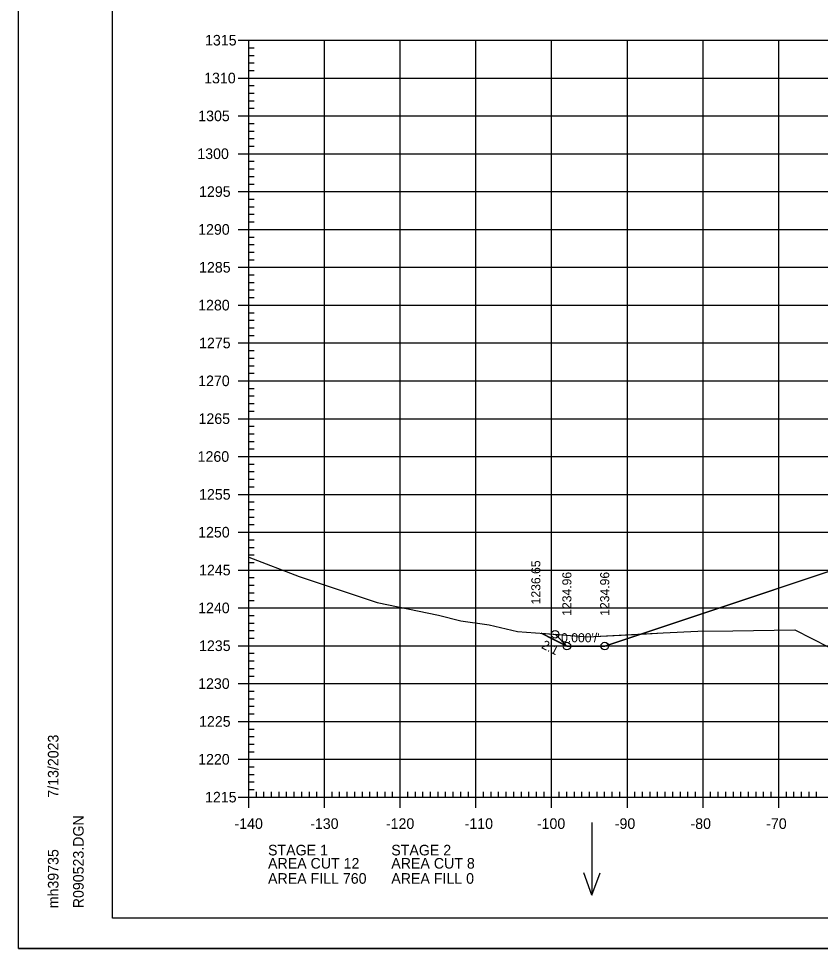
# Model space of a CAD drawing. Extents: x 1406028 to 1412453, y 321733 to 325986.
# Drawn here: x 1406419.5 to 1406525.4, y 324279.4 to 324402.2 of the extents above; entities that cross this region are included whole.
import ezdxf

# ---------------------------------------------------------------- set-up
doc = ezdxf.new("R2010")
doc.units = 0
for name, color, linetype in [('R_Axis', 7, 'Continuous'), ('R_Axis Annot', 7, 'Continuous'), ('R_Border', 7, 'Continuous'), ('R_Exist Surface', 7, 'Continuous'), ('R_Fin Surface', 7, 'Continuous'), ('R_Fin Surface Annot', 7, 'Continuous'), ('R_Grid', 7, 'Continuous'), ('R_No Plot', 7, 'Continuous'), ('R_Proposed Const Limits', 7, 'Continuous'), ('R_Proposed Road', 7, 'Continuous'), ('R_Water Annot', 7, 'Continuous')]:
    doc.layers.add(name, color=color, linetype=linetype)

msp = doc.modelspace()

# ---------------------------------------------------------------- linework, layer by layer
at = {"layer": 'R_Axis'}
for p, q in [((1406448.49, 324399.37), (1406451.29, 324399.37)), ((1406449.89, 324299.37), (1406449.89, 324399.37)), ((1406449.89, 324398.37), (1406450.59, 324398.37)), ((1406449.89, 324397.37), (1406450.59, 324397.37)), ((1406449.89, 324396.37), (1406450.59, 324396.37)), ((1406449.89, 324395.37), (1406450.59, 324395.37)), ((1406448.49, 324394.37), (1406451.29, 324394.37)), ((1406449.89, 324393.37), (1406450.59, 324393.37)), ((1406449.89, 324392.37), (1406450.59, 324392.37)), ((1406449.89, 324391.37), (1406450.59, 324391.37)), ((1406449.89, 324390.37), (1406450.59, 324390.37)), ((1406448.49, 324389.37), (1406451.29, 324389.37)), ((1406449.89, 324388.37), (1406450.59, 324388.37)), ((1406449.89, 324387.37), (1406450.59, 324387.37)), ((1406449.89, 324386.37), (1406450.59, 324386.37)), ((1406449.89, 324385.37), (1406450.59, 324385.37)), ((1406448.49, 324384.37), (1406451.29, 324384.37)), ((1406449.89, 324383.37), (1406450.59, 324383.37)), ((1406449.89, 324382.37), (1406450.59, 324382.37)), ((1406449.89, 324381.37), (1406450.59, 324381.37)), ((1406449.89, 324380.37), (1406450.59, 324380.37)), ((1406448.49, 324379.37), (1406451.29, 324379.37)), ((1406449.89, 324378.37), (1406450.59, 324378.37)), ((1406449.89, 324377.37), (1406450.59, 324377.37)), ((1406449.89, 324376.37), (1406450.59, 324376.37)), ((1406449.89, 324375.37), (1406450.59, 324375.37)), ((1406448.49, 324374.37), (1406451.29, 324374.37)), ((1406449.89, 324373.37), (1406450.59, 324373.37)), ((1406449.89, 324372.37), (1406450.59, 324372.37)), ((1406449.89, 324371.37), (1406450.59, 324371.37)), ((1406449.89, 324370.37), (1406450.59, 324370.37)), ((1406448.49, 324369.37), (1406451.29, 324369.37)), ((1406449.89, 324368.37), (1406450.59, 324368.37)), ((1406449.89, 324367.37), (1406450.59, 324367.37)), ((1406449.89, 324366.37), (1406450.59, 324366.37)), ((1406449.89, 324365.37), (1406450.59, 324365.37)), ((1406448.49, 324364.37), (1406451.29, 324364.37)), ((1406449.89, 324363.37), (1406450.59, 324363.37)), ((1406449.89, 324362.37), (1406450.59, 324362.37)), ((1406449.89, 324361.37), (1406450.59, 324361.37)), ((1406449.89, 324360.37), (1406450.59, 324360.37)), ((1406448.49, 324359.37), (1406451.29, 324359.37)), ((1406449.89, 324358.37), (1406450.59, 324358.37)), ((1406449.89, 324357.37), (1406450.59, 324357.37)), ((1406449.89, 324356.37), (1406450.59, 324356.37)), ((1406449.89, 324355.37), (1406450.59, 324355.37)), ((1406448.49, 324354.37), (1406451.29, 324354.37)), ((1406449.89, 324353.37), (1406450.59, 324353.37)), ((1406449.89, 324352.37), (1406450.59, 324352.37)), ((1406449.89, 324351.37), (1406450.59, 324351.37)), ((1406449.89, 324350.37), (1406450.59, 324350.37)), ((1406448.49, 324349.37), (1406451.29, 324349.37)), ((1406449.89, 324348.37), (1406450.59, 324348.37)), ((1406449.89, 324347.37), (1406450.59, 324347.37)), ((1406449.89, 324346.37), (1406450.59, 324346.37)), ((1406448.49, 324344.37), (1406451.29, 324344.37)), ((1406449.89, 324345.37), (1406450.59, 324345.37)), ((1406449.89, 324343.37), (1406450.59, 324343.37)), ((1406449.89, 324342.37), (1406450.59, 324342.37)), ((1406449.89, 324341.37), (1406450.59, 324341.37)), ((1406448.49, 324339.37), (1406451.29, 324339.37)), ((1406449.89, 324340.37), (1406450.59, 324340.37)), ((1406449.89, 324338.37), (1406450.59, 324338.37)), ((1406449.89, 324337.37), (1406450.59, 324337.37)), ((1406449.89, 324336.37), (1406450.59, 324336.37)), ((1406449.89, 324335.37), (1406450.59, 324335.37)), ((1406448.49, 324334.37), (1406451.29, 324334.37)), ((1406449.89, 324333.37), (1406450.59, 324333.37)), ((1406449.89, 324332.37), (1406450.59, 324332.37)), ((1406449.89, 324331.37), (1406450.59, 324331.37)), ((1406449.89, 324330.37), (1406450.59, 324330.37)), ((1406448.49, 324329.37), (1406451.29, 324329.37)), ((1406449.89, 324328.37), (1406450.59, 324328.37)), ((1406449.89, 324327.37), (1406450.59, 324327.37)), ((1406449.89, 324326.37), (1406450.59, 324326.37)), ((1406449.89, 324325.37), (1406450.59, 324325.37)), ((1406448.49, 324324.37), (1406451.29, 324324.37)), ((1406449.89, 324323.37), (1406450.59, 324323.37)), ((1406449.89, 324322.37), (1406450.59, 324322.37)), ((1406449.89, 324321.37), (1406450.59, 324321.37)), ((1406449.89, 324320.37), (1406450.59, 324320.37)), ((1406448.49, 324319.37), (1406451.29, 324319.37)), ((1406449.89, 324318.37), (1406450.59, 324318.37)), ((1406449.89, 324317.37), (1406450.59, 324317.37)), ((1406449.89, 324316.37), (1406450.59, 324316.37)), ((1406449.89, 324315.37), (1406450.59, 324315.37)), ((1406448.49, 324314.37), (1406451.29, 324314.37)), ((1406449.89, 324313.37), (1406450.59, 324313.37)), ((1406449.89, 324312.37), (1406450.59, 324312.37)), ((1406449.89, 324311.37), (1406450.59, 324311.37)), ((1406449.89, 324310.37), (1406450.59, 324310.37)), ((1406448.49, 324309.37), (1406451.29, 324309.37)), ((1406449.89, 324308.37), (1406450.59, 324308.37)), ((1406449.89, 324307.37), (1406450.59, 324307.37)), ((1406449.89, 324306.37), (1406450.59, 324306.37)), ((1406449.89, 324305.37), (1406450.59, 324305.37)), ((1406448.49, 324304.37), (1406451.29, 324304.37)), ((1406449.89, 324303.37), (1406450.59, 324303.37)), ((1406449.89, 324302.37), (1406450.59, 324302.37)), ((1406449.89, 324301.37), (1406450.59, 324301.37)), ((1406449.89, 324297.97), (1406449.89, 324300.77)), ((1406449.89, 324300.37), (1406450.59, 324300.37)), ((1406450.89, 324299.37), (1406450.89, 324300.07)), ((1406451.89, 324299.37), (1406451.89, 324300.07)), ((1406452.89, 324299.37), (1406452.89, 324300.07)), ((1406453.89, 324299.37), (1406453.89, 324300.07)), ((1406454.89, 324299.37), (1406454.89, 324300.07)), ((1406455.89, 324299.37), (1406455.89, 324300.07)), ((1406456.89, 324299.37), (1406456.89, 324300.07)), ((1406457.89, 324299.37), (1406457.89, 324300.07)), ((1406458.89, 324299.37), (1406458.89, 324300.07)), ((1406459.89, 324297.97), (1406459.89, 324300.77)), ((1406460.89, 324299.37), (1406460.89, 324300.07)), ((1406461.89, 324299.37), (1406461.89, 324300.07)), ((1406462.89, 324299.37), (1406462.89, 324300.07)), ((1406463.89, 324299.37), (1406463.89, 324300.07)), ((1406464.89, 324299.37), (1406464.89, 324300.07)), ((1406465.89, 324299.37), (1406465.89, 324300.07)), ((1406466.89, 324299.37), (1406466.89, 324300.07)), ((1406467.89, 324299.37), (1406467.89, 324300.07)), ((1406468.89, 324299.37), (1406468.89, 324300.07)), ((1406469.89, 324297.97), (1406469.89, 324300.77)), ((1406470.89, 324299.37), (1406470.89, 324300.07)), ((1406471.89, 324299.37), (1406471.89, 324300.07)), ((1406472.89, 324299.37), (1406472.89, 324300.07)), ((1406473.89, 324299.37), (1406473.89, 324300.07)), ((1406474.89, 324299.37), (1406474.89, 324300.07)), ((1406475.89, 324299.37), (1406475.89, 324300.07)), ((1406476.89, 324299.37), (1406476.89, 324300.07)), ((1406477.89, 324299.37), (1406477.89, 324300.07)), ((1406478.89, 324299.37), (1406478.89, 324300.07)), ((1406479.89, 324297.97), (1406479.89, 324300.77)), ((1406480.89, 324299.37), (1406480.89, 324300.07)), ((1406481.89, 324299.37), (1406481.89, 324300.07)), ((1406482.89, 324299.37), (1406482.89, 324300.07)), ((1406483.89, 324299.37), (1406483.89, 324300.07)), ((1406484.89, 324299.37), (1406484.89, 324300.07)), ((1406485.89, 324299.37), (1406485.89, 324300.07)), ((1406486.89, 324299.37), (1406486.89, 324300.07)), ((1406487.89, 324299.37), (1406487.89, 324300.07)), ((1406488.89, 324299.37), (1406488.89, 324300.07)), ((1406489.89, 324297.97), (1406489.89, 324300.77)), ((1406490.89, 324299.37), (1406490.89, 324300.07)), ((1406491.89, 324299.37), (1406491.89, 324300.07)), ((1406492.89, 324299.37), (1406492.89, 324300.07)), ((1406493.89, 324299.37), (1406493.89, 324300.07)), ((1406494.89, 324299.37), (1406494.89, 324300.07)), ((1406495.89, 324299.37), (1406495.89, 324300.07)), ((1406496.89, 324299.37), (1406496.89, 324300.07)), ((1406497.89, 324299.37), (1406497.89, 324300.07)), ((1406498.89, 324299.37), (1406498.89, 324300.07)), ((1406499.89, 324297.97), (1406499.89, 324300.77)), ((1406500.89, 324299.37), (1406500.89, 324300.07)), ((1406501.89, 324299.37), (1406501.89, 324300.07)), ((1406502.89, 324299.37), (1406502.89, 324300.07)), ((1406503.89, 324299.37), (1406503.89, 324300.07)), ((1406504.89, 324299.37), (1406504.89, 324300.07)), ((1406505.89, 324299.37), (1406505.89, 324300.07)), ((1406506.89, 324299.37), (1406506.89, 324300.07)), ((1406507.89, 324299.37), (1406507.89, 324300.07)), ((1406508.89, 324299.37), (1406508.89, 324300.07)), ((1406509.89, 324297.97), (1406509.89, 324300.77)), ((1406510.89, 324299.37), (1406510.89, 324300.07)), ((1406511.89, 324299.37), (1406511.89, 324300.07)), ((1406512.89, 324299.37), (1406512.89, 324300.07)), ((1406513.89, 324299.37), (1406513.89, 324300.07)), ((1406514.89, 324299.37), (1406514.89, 324300.07)), ((1406515.89, 324299.37), (1406515.89, 324300.07)), ((1406516.89, 324299.37), (1406516.89, 324300.07)), ((1406517.89, 324299.37), (1406517.89, 324300.07)), ((1406518.89, 324299.37), (1406518.89, 324300.07)), ((1406519.89, 324297.97), (1406519.89, 324300.77)), ((1406520.89, 324299.37), (1406520.89, 324300.07)), ((1406521.89, 324299.37), (1406521.89, 324300.07)), ((1406522.89, 324299.37), (1406522.89, 324300.07)), ((1406523.89, 324299.37), (1406523.89, 324300.07)), ((1406524.89, 324299.37), (1406524.89, 324300.07)), ((1406448.49, 324299.37), (1406451.29, 324299.37)), ((1406449.89, 324299.37), (1406729.89, 324299.37))]:
    msp.add_line(p, q, dxfattribs=at)
at = {"layer": 'R_Border'}
for p, q in [((1406431.89, 324283.37), (1406431.89, 324488.83)), ((1406431.89, 324283.37), (1406431.89, 324283.37)), ((1406748.07, 324283.37), (1406431.89, 324283.37))]:
    msp.add_line(p, q, dxfattribs=at)
at = {"layer": 'R_Exist Surface'}
msp.add_lwpolyline([(1406449.89, 324331.08), (1406456.53, 324328.54), (1406458.91, 324327.74), (1406466.86, 324325.08), (1406474.94, 324323.39), (1406477.91, 324322.65), (1406481.64, 324322.12), (1406485.39, 324321.26), (1406488.96, 324320.99), (1406494.64, 324320.56), (1406504.61, 324321.08), (1406509.22, 324321.29), (1406513.83, 324321.35), (1406522.03, 324321.49), (1406528.77, 324318.04)], dxfattribs=at)
at = {"layer": 'R_Fin Surface'}
msp.add_line((1406491.9, 324319.33), (1406488.51, 324321.02), dxfattribs=at)
msp.add_lwpolyline([(1406488.51, 324321.02), (1406490.05, 324320.25), (1406491.9, 324319.33), (1406492.59, 324319.33), (1406496.9, 324319.33), (1406506.16, 324322.41), (1406558.92, 324340)], dxfattribs=at)
at = {"layer": 'R_Grid'}
for p, q in [((1406449.89, 324399.37), (1406729.89, 324399.37)), ((1406449.89, 324299.37), (1406449.89, 324399.37)), ((1406459.89, 324299.37), (1406459.89, 324399.37)), ((1406469.89, 324299.37), (1406469.89, 324399.37)), ((1406479.89, 324299.37), (1406479.89, 324399.37)), ((1406489.89, 324299.37), (1406489.89, 324399.37)), ((1406499.89, 324299.37), (1406499.89, 324399.37)), ((1406509.89, 324299.37), (1406509.89, 324399.37)), ((1406519.89, 324299.37), (1406519.89, 324399.37)), ((1406449.89, 324394.37), (1406729.89, 324394.37)), ((1406449.89, 324389.37), (1406729.89, 324389.37)), ((1406449.89, 324384.37), (1406729.89, 324384.37)), ((1406449.89, 324379.37), (1406729.89, 324379.37)), ((1406449.89, 324374.37), (1406729.89, 324374.37)), ((1406449.89, 324369.37), (1406729.89, 324369.37)), ((1406449.89, 324364.37), (1406729.89, 324364.37)), ((1406449.89, 324359.37), (1406729.89, 324359.37)), ((1406449.89, 324354.37), (1406729.89, 324354.37)), ((1406449.89, 324349.37), (1406729.89, 324349.37)), ((1406449.89, 324344.37), (1406729.89, 324344.37)), ((1406449.89, 324339.37), (1406729.89, 324339.37)), ((1406449.89, 324334.37), (1406729.89, 324334.37)), ((1406449.89, 324329.37), (1406729.89, 324329.37)), ((1406449.89, 324324.37), (1406729.89, 324324.37)), ((1406449.89, 324319.37), (1406729.89, 324319.37)), ((1406449.89, 324314.37), (1406729.89, 324314.37)), ((1406449.89, 324309.37), (1406729.89, 324309.37)), ((1406449.89, 324304.37), (1406729.89, 324304.37)), ((1406449.89, 324299.37), (1406729.89, 324299.37))]:
    msp.add_line(p, q, dxfattribs=at)
at = {"layer": 'R_No Plot'}
msp.add_line((1406419.49, 324279.39), (1406752.82, 324279.39), dxfattribs=at)
for points in [[(1406419.48, 324492.72), (1406752.82, 324492.72), (1406752.82, 324279.39), (1406419.48, 324279.39)], [(1406665.81, 324488.83), (1406685.43, 324488.83), (1406685.43, 324478.95), (1406701.54, 324478.95), (1406724.74, 324478.95), (1406724.74, 324454.62), (1406748.07, 324454.62), (1406748.07, 324283.37), (1406431.89, 324283.37), (1406431.89, 324488.83)], [(1406488.51, 324321.02), (1406494.64, 324320.56), (1406501.72, 324320.92), (1406496.92, 324319.33), (1406494.98, 324319.33), (1406491.92, 324319.32), (1406491.15, 324319.7)]]:
    msp.add_lwpolyline(points, close=True, dxfattribs=at)
msp.add_lwpolyline([(1406558.94, 324340), (1406501.72, 324320.92), (1406504.61, 324321.08), (1406509.22, 324321.29), (1406513.83, 324321.35), (1406522.03, 324321.49), (1406528.77, 324318.04)], dxfattribs=at)
for centre in [(1406490.35, 324320.88), (1406491.9, 324319.33), (1406496.9, 324319.33)]:
    msp.add_circle(centre, 0.5, dxfattribs=at)
at = {"layer": 'R_Proposed Const Limits'}
msp.add_lwpolyline([(1406496.9, 324319.33), (1406491.9, 324319.33), (1406490.35, 324320.88)], dxfattribs=at)
at = {"layer": 'R_Proposed Road'}
msp.add_lwpolyline([(1406559.89, 324340.32), (1406496.9, 324319.33)], dxfattribs=at)
at = {"layer": 'R_Water Annot'}
for p, q in [((1406495.22, 324296.01), (1406495.22, 324286.44)), ((1406495.22, 324286.44), (1406494.15, 324289.37)), ((1406495.22, 324286.44), (1406496.29, 324289.37))]:
    msp.add_line(p, q, dxfattribs=at)

# ---------------------------------------------------------------- texts
at = {"layer": 'R_Axis Annot'}
for s, p in [('1315', (1406444.11, 324398.67)), ('1310', (1406443.99, 324393.67)), ('1305', (1406443.21, 324388.67)), ('1300', (1406443.09, 324383.67)), ('1295', (1406443.32, 324378.67)), ('1290', (1406443.2, 324373.67)), ('1285', (1406443.32, 324368.67)), ('1280', (1406443.2, 324363.67)), ('1275', (1406443.32, 324358.67)), ('1270', (1406443.2, 324353.67)), ('1265', (1406443.25, 324348.67)), ('1260', (1406443.13, 324343.67)), ('1255', (1406443.32, 324338.67)), ('1250', (1406443.2, 324333.67)), ('1245', (1406443.32, 324328.67)), ('1240', (1406443.2, 324323.67)), ('1235', (1406443.32, 324318.67)), ('1230', (1406443.2, 324313.67)), ('1225', (1406443.32, 324308.67)), ('1220', (1406443.2, 324303.67)), ('1215', (1406444.11, 324298.67)), ('-140', (1406448, 324295.17)), ('-130', (1406458, 324295.17)), ('-120', (1406468, 324295.17)), ('-110', (1406478.4, 324295.17)), ('-100', (1406487.94, 324295.17)), ('-90', (1406498.23, 324295.17)), ('-80', (1406508.23, 324295.17)), ('-70', (1406518.23, 324295.17)), ('STAGE 1', (1406452.43, 324291.67)), ('STAGE 2', (1406468.71, 324291.67)), ('AREA CUT 12', (1406452.43, 324289.93)), ('AREA CUT 8', (1406468.71, 324289.93)), ('AREA FILL 760', (1406452.43, 324287.93)), ('AREA FILL 0', (1406468.71, 324287.93))]:
    msp.add_text(s, height=1.4, dxfattribs=at).set_placement(p)
at = {"layer": 'R_Border'}
for s, p in [('7/13/2023', (1406424.75, 324299.3)), ('R090523.DGN', (1406428.08, 324284.69)), ('mh39735', (1406424.75, 324284.69))]:
    msp.add_text(s, height=1.4, rotation=90, dxfattribs=at).set_placement(p)
at = {"layer": 'R_Fin Surface Annot'}
for s, rotation, p in [('1236.65', 90, (1406488.4, 324324.84)), ('1234.96', 90, (1406492.5, 324323.33)), ('1234.96', 90, (1406497.5, 324323.33)), ("0.000'/'", 0.0007, (1406491.14, 324319.83)), ('2:1', 333.43, (1406488.45, 324319.1))]:
    msp.add_text(s, height=1.2, rotation=rotation, dxfattribs=at).set_placement(p)
at = {"layer": 'R_No Plot'}
for p in [(1406456.49, 324328.49), (1406466.82, 324325.03), (1406477.86, 324322.6), (1406485.35, 324321.21), (1406509.18, 324321.24), (1406521.99, 324321.44), (1406494.6, 324320.51)]:
    msp.add_text('+', height=0.1, dxfattribs=at).set_placement(p)

doc.saveas('drawing.dxf')
